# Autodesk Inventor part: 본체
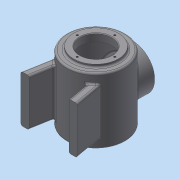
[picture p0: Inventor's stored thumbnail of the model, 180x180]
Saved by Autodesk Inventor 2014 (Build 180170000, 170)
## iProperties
Created: 2015-01
Part Number: 본체
Material: 일반
Document SubType Name: Modeling
Designer: user
Density: 1 g/cm^3
Appearance: 기본값
Author: user
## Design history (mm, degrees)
sketch "스케치1"
  geometry: C1 r 50 at (0, 0); 1 further point
  constraints: 1 centre point, 1 coincident
  dimensions: "d0" = 100 diameter of C1
extrude "돌출1" new body sketch "스케치1" stored distance "d1" = 112; taper "d2" = 0 deg
sketch "스케치2"
  geometry: C1 r 50 at (0, 0) reference; C2 r 38 at (0, 0)
  constraints: 1 centre point, 1 coincident
  dimensions: "d3" = 76 diameter of C2
extrude "돌출2" join sketch "스케치2" distance "d4" = 5; taper "d5" = 0 deg
sketch "스케치3"
  geometry: C1 r 50 at (0, 0) reference; C2 r 38 at (0, 0)
  constraints: 1 centre point, 1 coincident
  dimensions: "d6" = 76 diameter of C2
extrude "돌출3" join sketch "스케치3" distance "d7" = 5; taper "d8" = 0 deg
node "작업 평면2"
  node "작업 평면1"
sketch "스케치4"
  geometry: C1 r 38 at (0, 0); 1 further point
  constraints: 1 centre point, 1 coincident
  dimensions: "d10" = 76 diameter of C1
extrude "돌출4" join sketch "스케치4" stored distance "d11" = 5; taper "d12" = 0 deg
sketch "스케치5"
  geometry: L1 (-38.537, -26.331)-(-48, -80); L2 (-48, -80)-(-34, -80); L3 (-34, -80)-(-26.65, -38.317); L4 (38.537, -26.331)-(48, -80); L5 (48, -80)-(34, -80); L6 (34, -80)-(26.65, -38.317); L7 (-34, -80)-(67.419, -80); C1 r 50 at (0, 0) reference; A1 r 46.673 centre (0, 0) between (-38.537, -26.331) and (-26.65, -38.317); A2 r 46.673 centre (0, 0) between (26.65, -38.317) and (38.537, -26.331); 1 further point
  constraints: 14 end point, 4 point on circle, 3 equal length, 2 centre point, 2 horizontal, 2 parallel, 1 collinear, 1 horizontal alignment
  dimensions: "d13" = 80 vertical distance of L4.end point (0, 0); "d14" = 80 deg angle of L7 L6; "d15" = 14 distance of L4.end L5.end; "d16" = 96 distance of L4.end L1.end; "d17" = 48 horizontal distance of L4.end point (0, 0); "d19" = 46.67342 radius of A1
extrude "돌출5" join sketch "스케치5" stored distance "d20" = 80; taper "d21" = 0 deg
sketch "스케치6"
  geometry: C1 r 38 at (0, 0) reference; 1 further point
  constraints: 1 coincident
hole "구멍1" sketch "스케치6" at (0, 0) diameter "d22" = 54; stored, may be unused: countersink angle "d26" = 90 deg, drill point angle "d28" = 0 deg; dims "d23" = 6, "d24" = 4, "d25" = 2, "d27" = 13
sketch "스케치7"
  geometry: C1 r 27 at (0, 0) reference; 1 further point
  constraints: 1 coincident
hole "구멍2" sketch "스케치7" at (0, 0) diameter "d29" = 90; stored, may be unused: countersink angle "d33" = 90 deg, drill point angle "d35" = 0 deg; dims "d30" = 6, "d31" = 4, "d32" = 2, "d34" = 97
sketch "스케치8"
  geometry: C1 r 38 at (0, 0) reference; 1 further point
  constraints: 1 coincident
hole "구멍3" sketch "스케치8" at (0, 0) diameter "d36" = 54; stored, may be unused: countersink angle "d40" = 90 deg, drill point angle "d42" = 0 deg; dims "d37" = 6, "d38" = 4, "d39" = 2, "d41" = 12
sketch "스케치9"
  geometry: C1 r 38 at (0, 0) reference; 1 further point
  constraints: 1 coincident
hole "구멍4" sketch "스케치9" at (0, 0) diameter "d43" = 54; stored, may be unused: countersink angle "d47" = 90 deg, drill point angle "d49" = 0 deg; dims "d44" = 6, "d45" = 4, "d46" = 2, "d48" = 12
sketch "스케치10" dims "d50" = 64
  geometry: C1 r 27 at (0, 0) reference; C2 r 38 at (0, 0) reference; 2 further points
  constraints: 2 vertical alignment, 1 coincident, 2 other
hole "구멍5" sketch "스케치10" at (0, 32) diameter "d51" = 3.242; stored, may be unused: countersink angle "d55" = 90 deg, drill point angle "d57" = 118 deg; dims "d52" = 8, "d53" = 4, "d54" = 2, "d56" = 10
sketch "스케치11" dims "d61" = 64
  geometry: C1 r 27 at (0, 0) reference; C2 r 38 at (0, 0) reference; 2 further points
  constraints: 2 vertical alignment, 1 coincident, 2 other
hole "구멍6" sketch "스케치11" at (0, 32) diameter "d62" = 3.242; stored, may be unused: countersink angle "d66" = 90 deg, drill point angle "d68" = 118 deg; dims "d63" = 8, "d64" = 4, "d65" = 2, "d67" = 10
chamfer "모따기1" distance "d72" = 1; stored, may be unused: second distance "d73" = 2, angle "d74" = 45 deg
chamfer "모따기2" distance "d75" = 1; stored, may be unused: second distance "d76" = 2, angle "d77" = 45 deg
chamfer "모따기3" distance "d78" = 1; stored, may be unused: second distance "d79" = 2, angle "d80" = 45 deg
fillet "모깎기1" dims "d81" = 3
fillet "모깎기2" dims "d82" = 3
node "작업 평면4"
  node "작업 평면3"
sketch "스케치12"
  geometry: L1 (-6, -26)-(6, -26); L2 (6, -26)-(6, 28); L3 (6, 28)-(-6, 28); L4 (-6, 28)-(-6, -26); L5 (-6, 1)-(6, 1); L6 (38, 61)-(-38, 61) reference; L7 (-50, -53)-(50, -53) reference; 3 further points
  constraints: 10 end point, 4 midpoint, 2 parallel, 1 horizontal, 1 perpendicular, 1 vertical alignment
  dimensions: "d84" = 54 distance of L3.end L1.start; "d85" = 12 distance of L1.start L1.end; "d86" = 60 distance between parallel lines of L6 L5
extrude "돌출6" join sketch "스케치12" stored distance "d87" = 10; taper "d88" = 0 deg
sketch "스케치13"
  geometry: L1 (-26, 6)-(-26, -6) reference; L2 (28, 6)-(-26, 6) reference; 4 further points
  constraints: 2 midpoint, 1 horizontal alignment, 1 vertical alignment, 1 other
feature "엠보싱1" sketch "스케치13" dims "d11" = 5, "d12" = 0, "d89" = 0.5, "d90" = 0
fillet "모깎기3" dims "d91" = 3
node "솔리드1"
pattern_circular "원형 패턴1" dims angle "d59" = 360 deg
mirror "대칭1"
pattern_circular "원형 패턴2" dims angle "d70" = 360 deg
other parameters: "d9" = 12, "d83" = 2
